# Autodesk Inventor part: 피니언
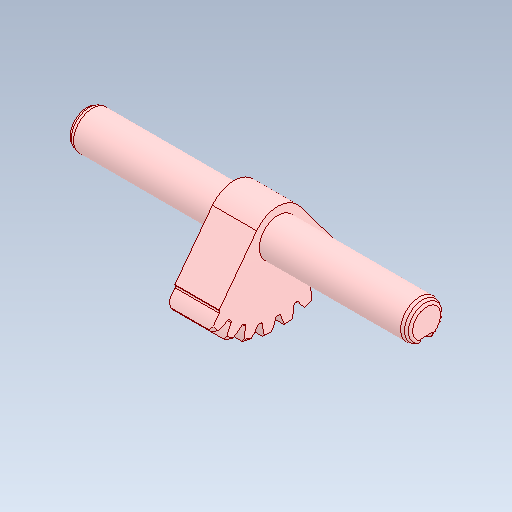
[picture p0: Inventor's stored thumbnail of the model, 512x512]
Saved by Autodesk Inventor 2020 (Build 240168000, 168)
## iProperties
Created: 2024-07
Part Number: 피니언
Material: 강철, 탄소
Document SubType Name: Modeling
Designer: oem
Density: 7.85 g/cm^3
Appearance: 기본값
Author: jhkim
Sending System: Autodesk Inventor 2025
Preprocessor: ST-DEVELOPER v20
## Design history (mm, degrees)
feature "솔리드1"
node "솔리드2"
